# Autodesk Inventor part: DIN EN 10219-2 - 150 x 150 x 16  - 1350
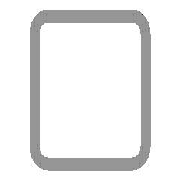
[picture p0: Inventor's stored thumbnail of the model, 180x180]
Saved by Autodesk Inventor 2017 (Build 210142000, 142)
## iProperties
Created: 2016-02
Part Number: DIN EN 10219-2 - 150 x 150 x 16  - 1350
Material: Steel, Mild
Description: Cold formed welded structural hollow sections of non-alloy and fine grain structural steel
Document SubType Name: Modeling
Standard: DIN
Designer: iusti
Standard Revision: 2006-07
Standards Organization: DIN
Language: en-US
Size Designation: 150 x 150 x 16
Categories: <MemberInstance><Categories><Category DisplayName="Structural Shapes" InternalName="089c4875-fa83-4c05-b084-43b9cc11f5ed" Mnemonic="GRDR"><CategoryParameter Dis
Stock Number: 150 x 150 x 16
Mass: 79240 g
Surface Area: 12767.4 cm^2
Volume: 10094.3 cm^3
Density: 7.85 g/cm^3
Appearance: Semi-Polished
_CCFamilyMember: 76
_CCFamilyDisplayName: DIN EN 10219-2 (Square Hollow Section - Cold Formed) - Cold formed welded structural hollow sections of non-alloy and fine grain structural steel
_FrameMemberDoc: Frame Member File
_Version: 15.0.0
_GetPNFromCC: 1
IsCustomPart: 1
G_L: 1350.000 mm
G_W: 150.000 mm
G_H: 150.000 mm
+9B96A9D1-53DA-4299-ADB7-BA59D95C451C+CUTDETAIL1: Cut
+EC60967C-127F-4733-B979-3413A57744B4+CUTDETAIL2: Cut
Author: iusti
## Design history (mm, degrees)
node "Start plane"
node "End plane"
sketch "Sketch"
  geometry: L1 (-75, -27)-(-75, 27); L2 (-27, 75)-(27, 75); L3 (75, 27)-(75, -27); L4 (27, -75)-(-27, -75); L5 (-27, 59)-(27, 59); L6 (59, 27)-(59, -27); L7 (27, -59)-(-27, -59); L8 (-59, -27)-(-59, 27); L9 (0, 118.918)-(0, -118.918) reference; L10 (-118.918, 0)-(118.918, 0) reference; A1 r 48 centre (-27, -27) between (-75, -27) and (-27, -75); A2 r 48 centre (-27, 27) between (-27, 75) and (-75, 27); A3 r 48 centre (27, 27) between (75, 27) and (27, 75); A4 r 48 centre (27, -27) between (27, -75) and (75, -27); A5 r 32 centre (-27, 27) between (-27, 59) and (-59, 27); A6 r 32 centre (27, 27) between (59, 27) and (27, 59); A7 r 32 centre (27, -27) between (27, -59) and (59, -27); A8 r 32 centre (-27, -27) between (-59, -27) and (-27, -59)
  constraints: 16 end point, 16 point on circle, 8 centre point, 8 tangent, 4 parallel, 3 equal radius, 2 perpendicular, 7 other
  dimensions: "d7" = 48 radius of A1 (= G_IR); "d10" = 150 distance between parallel lines of L2 L4 (= G_H); "d11" = 150 distance between parallel lines of L1 L3 (= G_W); "d12" = 16 distance between parallel lines of L3 L6 (= G_T); "d15" = 75 distance between parallel lines of L2 L10 (= 0.5 x d10); "d16" = 75 distance between parallel lines of L9 L3 (= 0.5 x d11)
extrude "Body" new body sketch "Sketch" stored distance "d3" = 1350 (= G_L); taper "d4" = 0 deg
node "Driven Length"
  sketch "Sketch3"
    geometry: L1 (0, 0)-(10, 0) reference
    constraints: 2 end point, 1 horizontal
  workplane "Work Plane3"
  sketch "Sketch4"
    geometry: L1 (-2, 75)-(12, 75) reference; L2 (-2, 1425)-(12, 1425) reference
    dimensions: "d18" = 1350 distance between parallel lines of L1 L2 (derived)
workplane "Work Plane4"
split "Split1"
workplane "Work Plane5"
split "Split2"
body "Solid1"
other parameters: "G_W" = 150 [user parameter; used in 1 equation term], "G_H" = 150 [user parameter; used in 1 equation term], "G_T" = 16 [user parameter; used in 1 equation term], "G_IR" = 48 [user parameter; used in 1 equation term], "G_L" = 1350 (= d18) [user parameter; used in 1 equation term], "G_OFFSET_START" = -75 [user parameter; used in 1 equation term], "G_OFFSET_END" = -75 [user parameter; used in 1 equation term], "d13" = 75 (= -G_OFFSET_START), "d14" = 1425 (= G_OFFSET_END + B_L), "d17" = 90 deg
